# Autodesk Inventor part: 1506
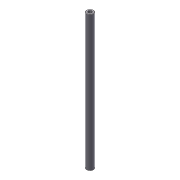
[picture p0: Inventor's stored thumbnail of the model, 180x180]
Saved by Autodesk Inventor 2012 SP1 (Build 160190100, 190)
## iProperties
Created: 2012-02
Part Number: 1506
Material: Aluminum-6061
Document SubType Name: Modeling
Designer: LACO
Density: 2.71 g/cm^3
Mass: 35.6187 g
Surface Area: 62.6624 cm^2
Volume: 13.1434 cm^3
Author: LACO
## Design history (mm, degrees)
sketch "Sketch1"
  geometry: C1 r 4.763 at (0, 0); 1 further point
  constraints: 1 centre point, 1 coincident
  dimensions: "d0" = 9.525 diameter of C1
extrude "base" new body sketch "Sketch1" stored distance "d1" = 189.23; taper "d2" = 0 deg
hole "Hole1" diameter "d5" = 4.9784; stored, may be unused: countersink angle "d9" = 82 deg, drill point angle "d11" = 118 deg; dims "d6" = 10.16, "d7" = 9.525, "d8" = 6.35, "d10" = 12.7, "d28" = 25.4, "d29" = 25.4
hole "Hole2" diameter "d14" = 4.9784; stored, may be unused: countersink angle "d18" = 82 deg, drill point angle "d20" = 118 deg; dims "d15" = 10.16, "d16" = 9.525, "d17" = 6.35, "d19" = 12.7, "d24" = 25.4, "d25" = 25.4
chamfer "Chamfer1" distance "d21" = 0.508; stored, may be unused: second distance "d22" = 3.175, angle "d23" = 45 deg
body "Solid1"
